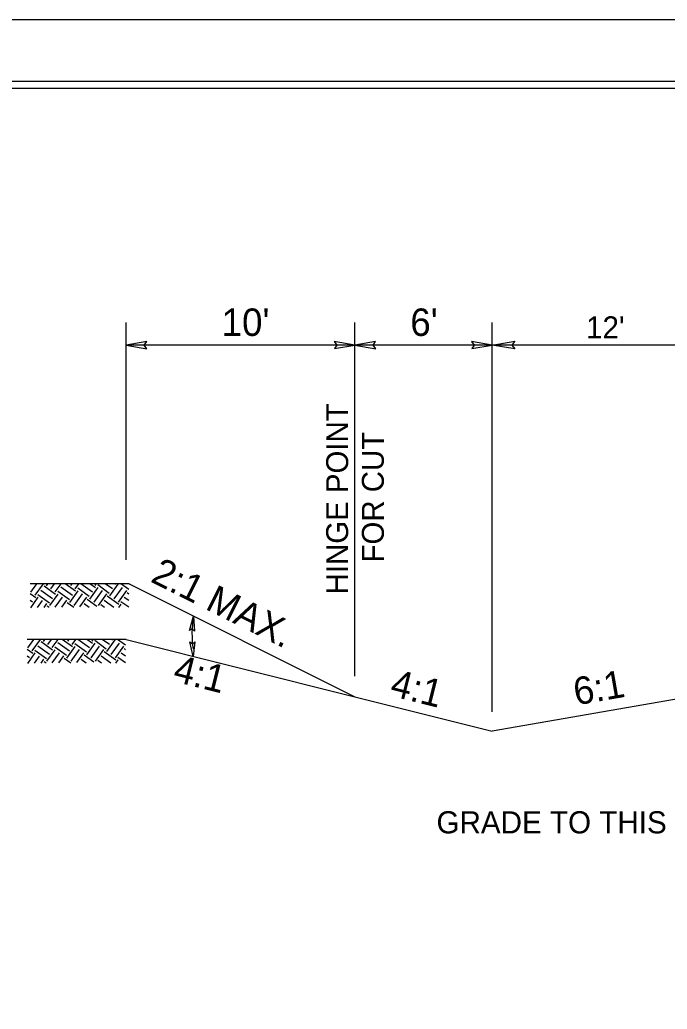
# Model space of a CAD drawing. Extents: x 3025871 to 3026431, y 707165 to 707825.
# Drawn here: x 3026105.8 to 3026141.1, y 707333.4 to 707387.4 of the extents above; entities that cross this region are included whole.
import ezdxf

# ---------------------------------------------------------------- set-up
doc = ezdxf.new("R2010")
doc.units = 0
for name, color, linetype in [('Old_Level_39', 7, 'Continuous'), ('Prop Drainage Structure Junction Box with Slab Lid TB 840 34 CELL', 7, 'Continuous'), ('Sheet Cutting Line CELL', 7, 'Continuous'), ('Typical Terminator CELL', 7, 'Continuous'), ('Typical Text Centerline CELL', 7, 'Continuous'), ('Typical Text Grade Point CELL', 7, 'Continuous')]:
    doc.layers.add(name, color=color, linetype=linetype)

msp = doc.modelspace()

# ---------------------------------------------------------------- linework, layer by layer
at = {"layer": 'Old_Level_39'}
msp.add_lwpolyline([(3026273.948, 707384.017), (3026023.973, 707384.017), (3026023.973, 707225.752), (3026273.948, 707225.752)], close=True, dxfattribs=at)
at = {"layer": 'Prop Drainage Structure Junction Box with Slab Lid TB 840 34 CELL'}
for p, q in [((3026111.573, 707357.91), (3026111.573, 707370.858)), ((3026124.073, 707351.544), (3026124.073, 707370.858)), ((3026131.573, 707349.606), (3026131.573, 707370.858)), ((3026124.073, 707369.624), (3026111.573, 707369.624)), ((3026131.573, 707369.624), (3026124.073, 707369.624)), ((3026143.573, 707369.624), (3026131.573, 707369.624))]:
    msp.add_line(p, q, dxfattribs=at)
msp.add_arc((3026121.286, 707353.866), 6.116, 171.0253, 187.9293, dxfattribs=at)
at = {"layer": 'Sheet Cutting Line CELL'}
msp.add_lwpolyline([(3026272.073, 707383.635), (3026047.073, 707383.635), (3026047.073, 707226.135), (3026272.073, 707226.135)], close=True, dxfattribs=at)
at = {"layer": 'Typical Terminator CELL'}
msp.add_lwpolyline([(3026274.623, 707387.385), (3026022.023, 707387.385), (3026022.023, 707222.385), (3026274.623, 707222.385)], close=True, dxfattribs=at)
at = {"layer": 'Typical Text Centerline CELL'}
for points in [[(3026112.698, 707369.818), (3026111.573, 707369.624), (3026112.704, 707369.424), (3026112.56, 707369.624)], [(3026122.948, 707369.431), (3026124.073, 707369.624), (3026122.941, 707369.824), (3026123.085, 707369.624)], [(3026125.198, 707369.818), (3026124.073, 707369.624), (3026125.204, 707369.424), (3026125.06, 707369.624)], [(3026130.448, 707369.431), (3026131.573, 707369.624), (3026130.441, 707369.824), (3026130.585, 707369.624)], [(3026132.798, 707369.413), (3026131.573, 707369.624), (3026132.805, 707369.842), (3026132.648, 707369.624)], [(3026115.032, 707354.048), (3026115.245, 707354.82), (3026115.307, 707354.016), (3026115.177, 707354.13)], [(3026115.324, 707353.427), (3026115.228, 707352.632), (3026115.048, 707353.418), (3026115.193, 707353.324)]]:
    msp.add_lwpolyline(points, close=True, dxfattribs=at)
at = {"layer": 'Typical Text Grade Point CELL'}
for p, q in [((3026111.732, 707356.587), (3026106.335, 707356.587)), ((3026106.373, 707356.141), (3026106.694, 707356.587)), ((3026106.611, 707355.97), (3026107.055, 707356.587)), ((3026107.724, 707356.012), (3026107.09, 707356.468)), ((3026107.226, 707356.491), (3026107.295, 707356.587)), ((3026107.464, 707356.32), (3026107.664, 707356.599)), ((3026107.702, 707356.149), (3026108.017, 707356.587)), ((3026108.644, 707355.953), (3026108.009, 707356.409)), ((3026108.815, 707356.191), (3026108.25, 707356.597)), ((3026108.555, 707356.498), (3026108.625, 707356.596)), ((3026108.793, 707356.327), (3026108.985, 707356.595)), ((3026109.734, 707356.131), (3026109.1, 707356.588)), ((3026109.586, 707355.757), (3026110.042, 707356.392)), ((3026109.906, 707356.369), (3026109.594, 707356.593)), ((3026109.883, 707356.506), (3026109.945, 707356.592)), ((3026110.654, 707356.072), (3026110.02, 707356.528)), ((3026110.825, 707356.31), (3026110.435, 707356.591)), ((3026110.676, 707355.936), (3026111.133, 707356.57)), ((3026110.914, 707355.765), (3026111.371, 707356.399)), ((3026110.996, 707356.548), (3026110.939, 707356.589)), ((3026111.712, 707356.275), (3026111.275, 707356.588)), ((3026111.732, 707356.587), (3026124.074, 707350.416)), ((3026106.633, 707355.834), (3026106.335, 707356.048)), ((3026106.361, 707355.288), (3026106.77, 707355.856)), ((3026107.382, 707355.536), (3026106.747, 707355.992)), ((3026107.553, 707355.774), (3026106.918, 707356.23)), ((3026107.404, 707355.4), (3026107.86, 707356.035)), ((3026107.704, 707355.315), (3026108.098, 707355.864)), ((3026108.473, 707355.715), (3026107.838, 707356.171)), ((3026108.495, 707355.579), (3026108.951, 707356.213)), ((3026108.733, 707355.408), (3026109.189, 707356.042)), ((3026109.563, 707355.894), (3026108.929, 707356.35)), ((3026109.047, 707355.342), (3026109.427, 707355.871)), ((3026109.824, 707355.586), (3026110.28, 707356.221)), ((3026110.062, 707355.415), (3026110.518, 707356.05)), ((3026111.175, 707355.457), (3026110.54, 707355.913)), ((3026111.152, 707355.594), (3026111.608, 707356.228)), ((3026111.712, 707355.673), (3026111.46, 707355.854)), ((3026111.712, 707356.034), (3026111.631, 707356.092)), ((3026106.462, 707355.596), (3026106.335, 707355.687)), ((3026106.728, 707355.295), (3026107.008, 707355.685)), ((3026107.094, 707355.303), (3026107.246, 707355.514)), ((3026107.365, 707355.308), (3026107.268, 707355.378)), ((3026108.07, 707355.322), (3026108.336, 707355.693)), ((3026108.721, 707355.296), (3026108.359, 707355.556)), ((3026109.558, 707355.296), (3026109.278, 707355.497)), ((3026109.971, 707355.36), (3026109.449, 707355.735)), ((3026110.395, 707355.296), (3026110.198, 707355.437)), ((3026110.897, 707355.296), (3026110.369, 707355.675)), ((3026111.179, 707355.296), (3026111.311, 707355.48)), ((3026111.712, 707355.312), (3026111.289, 707355.616)), ((3026111.568, 707353.548), (3026106.171, 707353.548)), ((3026106.209, 707353.102), (3026106.53, 707353.548)), ((3026106.447, 707352.931), (3026106.891, 707353.548)), ((3026107.389, 707352.735), (3026106.755, 707353.192)), ((3026107.56, 707352.973), (3026106.926, 707353.429)), ((3026107.062, 707353.452), (3026107.131, 707353.548)), ((3026107.3, 707353.281), (3026107.5, 707353.56)), ((3026107.538, 707353.11), (3026107.853, 707353.548)), ((3026108.309, 707352.676), (3026107.674, 707353.132)), ((3026108.48, 707352.914), (3026107.845, 707353.37)), ((3026108.651, 707353.152), (3026108.086, 707353.558)), ((3026108.331, 707352.54), (3026108.787, 707353.174)), ((3026108.391, 707353.459), (3026108.461, 707353.557)), ((3026108.629, 707353.288), (3026108.821, 707353.556)), ((3026109.4, 707352.855), (3026108.765, 707353.311)), ((3026109.571, 707353.093), (3026108.936, 707353.549)), ((3026109.422, 707352.718), (3026109.878, 707353.353)), ((3026109.742, 707353.331), (3026109.43, 707353.554)), ((3026109.66, 707352.547), (3026110.116, 707353.182)), ((3026109.719, 707353.467), (3026109.781, 707353.553)), ((3026110.49, 707353.033), (3026109.856, 707353.489)), ((3026110.661, 707353.271), (3026110.271, 707353.552)), ((3026110.513, 707352.897), (3026110.969, 707353.531)), ((3026110.751, 707352.726), (3026111.207, 707353.36)), ((3026110.832, 707353.509), (3026110.775, 707353.55)), ((3026110.989, 707352.555), (3026111.445, 707353.189)), ((3026111.548, 707353.236), (3026111.111, 707353.549)), ((3026111.568, 707353.548), (3026124.074, 707350.416)), ((3026106.47, 707352.795), (3026106.171, 707353.009)), ((3026106.299, 707352.557), (3026106.171, 707352.649)), ((3026106.198, 707352.249), (3026106.606, 707352.817)), ((3026106.564, 707352.256), (3026106.844, 707352.646)), ((3026107.218, 707352.497), (3026106.584, 707352.954)), ((3026107.241, 707352.361), (3026107.697, 707352.996)), ((3026107.54, 707352.276), (3026107.935, 707352.825)), ((3026107.906, 707352.283), (3026108.173, 707352.654)), ((3026108.569, 707352.369), (3026109.025, 707353.003)), ((3026108.883, 707352.303), (3026109.263, 707352.832)), ((3026109.807, 707352.321), (3026109.286, 707352.696)), ((3026109.898, 707352.376), (3026110.354, 707353.011)), ((3026110.733, 707352.257), (3026110.205, 707352.637)), ((3026111.011, 707352.418), (3026110.376, 707352.874)), ((3026111.548, 707352.273), (3026111.125, 707352.577)), ((3026111.548, 707352.634), (3026111.296, 707352.815)), ((3026111.548, 707352.995), (3026111.467, 707353.053)), ((3026106.93, 707352.264), (3026107.082, 707352.475)), ((3026107.201, 707352.269), (3026107.104, 707352.339)), ((3026108.557, 707352.257), (3026108.195, 707352.517)), ((3026109.394, 707352.257), (3026109.115, 707352.458)), ((3026110.231, 707352.257), (3026110.034, 707352.399)), ((3026111.015, 707352.257), (3026111.147, 707352.441)), ((3026124.074, 707350.416), (3026131.573, 707348.542)), ((3026143.573, 707350.633), (3026131.573, 707348.542))]:
    msp.add_line(p, q, dxfattribs=at)

# ---------------------------------------------------------------- texts
at = {"layer": 'Prop Drainage Structure Junction Box with Slab Lid TB 840 34 CELL'}
for s, height, p in [("10' ", 1.5, (3026116.79, 707370.124)), ("6' ", 1.5, (3026127.095, 707370.124)), ("12'", 1.2089, (3026136.694, 707369.986)), ('GRADE TO THIS LINE', 1.20892, (3026128.527, 707342.966))]:
    msp.add_text(s, height=height, dxfattribs=at).set_placement(p)
for s, p in [('HINGE POINT', (3026123.701, 707356.017)), ('FOR CUT', (3026125.651, 707357.758))]:
    msp.add_text(s, height=1.2, rotation=90, dxfattribs=at).set_placement(p)
at = {"layer": 'Typical Text Grade Point CELL'}
for s, rotation, p in [('2:1 MAX.', 333.435, (3026112.847, 707356.736)), ('4:1', 345.9638, (3026114.075, 707351.282)), ('4:1', 345.9638, (3026125.925, 707350.497)), ('6:1', 9.8836, (3026136.145, 707349.952))]:
    msp.add_text(s, height=1.5, rotation=rotation, dxfattribs=at).set_placement(p)

doc.saveas('drawing.dxf')
